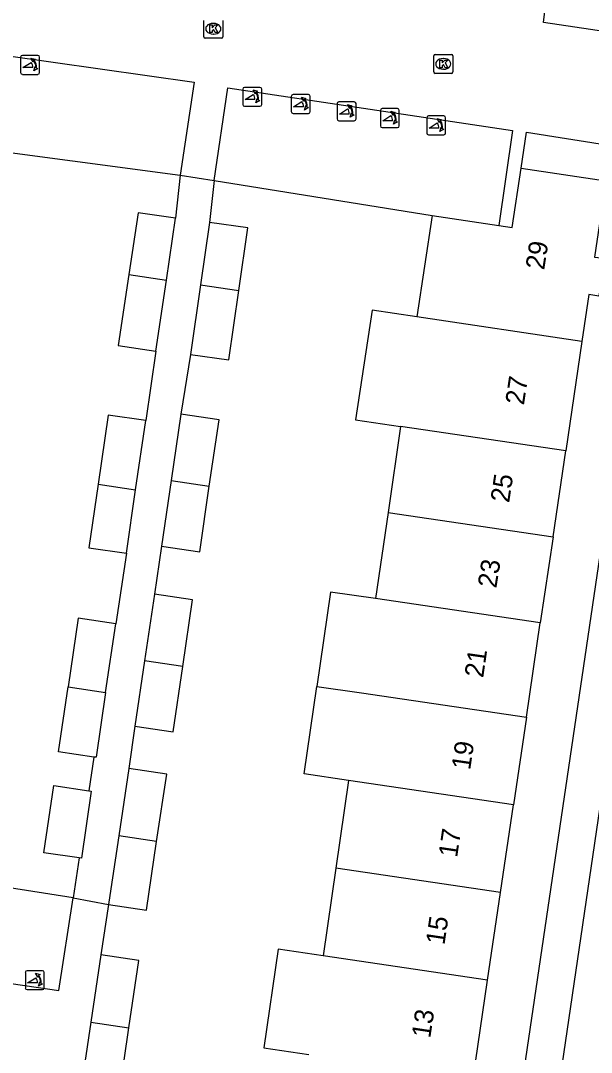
# Model space of a CAD drawing. Extents: x 164150 to 165261, y 382513 to 383432.
# Drawn here: x 164238.9 to 164268.9, y 382940.4 to 382994.8 of the extents above; entities that cross this region are included whole.
import ezdxf

# ---------------------------------------------------------------- set-up
doc = ezdxf.new("R2010")
doc.units = 0
for name, color, linetype in [('IMGEO_Kolk', 7, 'Continuous'), ('IMGEO_Pand', 7, 'Continuous'), ('IMGEO_Pand_nummerreeks', 7, 'Continuous'), ('IMGEO_Parkeervlak_open', 7, 'Continuous'), ('IMGEO_Poller', 7, 'Continuous'), ('IMGEO_Rijbaan_lokaal_open', 7, 'Continuous'), ('IMGEO_Voetpad_open', 7, 'Continuous')]:
    doc.layers.add(name, color=color, linetype=linetype)

msp = doc.modelspace()

# ---------------------------------------------------------------- linework, layer by layer
at = {"layer": 'IMGEO_Kolk'}
for p, q in [((164248.512, 382993.961), (164248.512, 382994.813)), ((164249.513, 382994.813), (164249.513, 382993.961)), ((164249, 382994.667), (164249.025, 382994.667)), ((164249.439, 382993.887), (164248.587, 382993.887)), ((164249.023, 382994.107), (164248.998, 382994.107)), ((164260.625, 382992.108), (164260.625, 382992.96)), ((164260.7, 382993.034), (164261.552, 382993.034)), ((164261.113, 382992.814), (164261.138, 382992.814)), ((164261.626, 382992.96), (164261.626, 382992.108)), ((164261.136, 382992.254), (164261.111, 382992.254)), ((164261.552, 382992.034), (164260.7, 382992.034))]:
    msp.add_line(p, q, dxfattribs=at)
for points in [[(164248.512, 382993.961), (164248.512, 382994.813)], [(164249.513, 382994.813), (164249.513, 382993.961)], [(164248.833, 382994.587), (164248.956, 382994.587), (164248.956, 382994.436), (164249.086, 382994.587), (164249.25, 382994.587), (164249.104, 382994.436), (164249.257, 382994.187), (164249.105, 382994.187), (164249.02, 382994.351), (164248.956, 382994.284), (164248.956, 382994.187), (164248.833, 382994.187), (164248.833, 382994.587)], [(164249.439, 382993.887), (164248.587, 382993.887)], [(164260.625, 382992.108), (164260.625, 382992.96)], [(164260.7, 382993.034), (164261.552, 382993.034)], [(164260.946, 382992.734), (164261.069, 382992.734), (164261.069, 382992.583), (164261.199, 382992.734), (164261.363, 382992.734), (164261.217, 382992.583), (164261.37, 382992.334), (164261.218, 382992.334), (164261.133, 382992.498), (164261.069, 382992.431), (164261.069, 382992.334), (164260.946, 382992.334), (164260.946, 382992.734)], [(164261.626, 382992.96), (164261.626, 382992.108)], [(164261.552, 382992.034), (164260.7, 382992.034)]]:
    msp.add_lwpolyline(points, dxfattribs=at)
for centre, start, end in [((164248.589, 382993.963), 181.552, 268.448), ((164248.589, 382993.963), 181.552, 268.448), ((164249.437, 382993.963), 271.552, 358.448), ((164249.437, 382993.963), 271.552, 358.448), ((164260.702, 382992.958), 91.552, 178.448), ((164260.702, 382992.958), 91.552, 178.448), ((164261.55, 382992.958), 1.552, 88.448), ((164261.55, 382992.958), 1.552, 88.448), ((164260.702, 382992.11), 181.552, 268.448), ((164260.702, 382992.11), 181.552, 268.448), ((164261.55, 382992.11), 271.552, 358.448), ((164261.55, 382992.11), 271.552, 358.448)]:
    msp.add_arc(centre, 0.0765, start, end, dxfattribs=at)
for centre, major_axis, ratio, start_param, end_param in [((164248.999, 382994.387), (-0.387, 0.002), 0.722429, 4.712389, 7.853982), ((164249.024, 382994.387), (-0.39, 0.002), 0.717154, 1.570796, 4.712389), ((164261.112, 382992.534), (-0.387, 0.002), 0.722429, 4.712389, 7.853982), ((164261.137, 382992.534), (-0.39, 0.002), 0.717154, 1.570796, 4.712389)]:
    msp.add_ellipse(centre, major_axis=major_axis, ratio=ratio, start_param=start_param, end_param=end_param, dxfattribs=at)
at = {"layer": 'IMGEO_Pand'}
for points in [[(164264.054, 382984.022), (164264.753, 382983.919), (164265.229, 382987.03)], [(164265.229, 382987.03), (164269.688, 382986.378), (164269.099, 382982.348), (164269.632, 382982.3), (164269.326, 382980.293), (164268.792, 382980.375), (164268.428, 382977.911)], [(164247.024, 382984.396), (164245.046, 382984.689), (164244.562, 382981.432)], [(164260.536, 382984.54), (164259.733, 382979.198)], [(164260.536, 382984.54), (164264.054, 382984.022)], [(164246.541, 382981.139), (164247.024, 382984.396)], [(164248.815, 382984.183), (164248.34, 382980.884)], [(164250.355, 382980.586), (164250.832, 382983.893), (164248.815, 382984.183)], [(164244.562, 382981.432), (164244.007, 382977.691), (164245.986, 382977.397)], [(164244.562, 382981.432), (164246.541, 382981.139)], [(164245.986, 382977.397), (164246.541, 382981.139)], [(164248.34, 382980.884), (164247.812, 382977.22)], [(164248.34, 382980.884), (164250.355, 382980.586)], [(164247.812, 382977.22), (164249.829, 382976.93), (164250.355, 382980.586)], [(164259.733, 382979.198), (164257.371, 382979.553), (164256.504, 382973.779), (164258.877, 382973.423)], [(164268.428, 382977.911), (164259.733, 382979.198)], [(164268.428, 382977.911), (164267.576, 382972.135)], [(164245.448, 382973.734), (164243.468, 382974.022), (164242.939, 382970.38)], [(164244.917, 382970.087), (164245.448, 382973.734)], [(164247.307, 382974.069), (164246.793, 382970.58)], [(164248.801, 382970.283), (164249.315, 382973.774), (164247.307, 382974.069)], [(164258.877, 382973.423), (164258.219, 382968.889)], [(164267.576, 382972.135), (164258.877, 382973.423)], [(164266.907, 382967.603), (164267.576, 382972.135)], [(164242.939, 382970.38), (164242.453, 382967.035), (164244.432, 382966.748)], [(164242.939, 382970.38), (164244.917, 382970.087)], [(164246.793, 382970.58), (164246.284, 382967.115)], [(164246.793, 382970.58), (164248.801, 382970.283)], [(164244.432, 382966.748), (164244.917, 382970.087)], [(164246.284, 382967.115), (164248.292, 382966.82), (164248.801, 382970.283)], [(164258.219, 382968.889), (164257.561, 382964.355)], [(164258.219, 382968.889), (164266.907, 382967.603)], [(164266.907, 382967.603), (164266.238, 382963.071)], [(164245.907, 382964.58), (164245.39, 382961.076)], [(164247.398, 382960.779), (164247.915, 382964.284), (164245.907, 382964.58)], [(164257.561, 382964.355), (164255.186, 382964.7), (164254.463, 382959.727)], [(164266.238, 382963.071), (164257.561, 382964.355)], [(164243.867, 382963.027), (164241.888, 382963.317), (164241.359, 382959.696)], [(164243.337, 382959.403), (164243.867, 382963.027)], [(164265.504, 382958.099), (164266.238, 382963.071)], [(164245.39, 382961.076), (164244.881, 382957.624)], [(164247.398, 382960.779), (164245.39, 382961.076)], [(164244.881, 382957.624), (164246.889, 382957.328), (164247.398, 382960.779)], [(164242.721, 382956.006), (164240.859, 382956.278), (164241.359, 382959.696)], [(164241.359, 382959.696), (164243.337, 382959.403)], [(164256.139, 382954.767), (164253.792, 382955.114), (164254.463, 382959.727)], [(164254.463, 382959.727), (164256.81, 382959.386), (164265.504, 382958.099)], [(164243.337, 382959.403), (164242.838, 382955.989), (164242.721, 382956.006)], [(164265.504, 382958.099), (164264.822, 382953.482)], [(164244.553, 382955.398), (164244.028, 382951.843)], [(164246.026, 382951.547), (164246.557, 382955.102), (164244.553, 382955.398)], [(164256.139, 382954.767), (164255.468, 382950.15)], [(164264.822, 382953.482), (164256.139, 382954.767)], [(164241.939, 382950.687), (164240.08, 382950.961), (164240.602, 382954.496), (164242.46, 382954.222)], [(164242.46, 382954.222), (164242.58, 382954.204), (164242.059, 382950.669), (164241.939, 382950.687)], [(164264.141, 382948.866), (164264.822, 382953.482)], [(164244.028, 382951.843), (164243.515, 382948.363), (164243.495, 382948.226)], [(164246.026, 382951.547), (164244.028, 382951.843)], [(164243.495, 382948.226), (164245.485, 382947.932), (164246.026, 382951.547)], [(164255.468, 382950.15), (164254.797, 382945.531)], [(164264.141, 382948.866), (164255.468, 382950.15)], [(164263.459, 382944.249), (164264.141, 382948.866)], [(164254.797, 382945.531), (164252.432, 382945.875), (164251.678, 382940.679), (164254.043, 382940.336)], [(164243.081, 382945.579), (164242.558, 382942.035)], [(164244.566, 382941.738), (164245.089, 382945.283), (164243.081, 382945.579)], [(164263.459, 382944.249), (164254.797, 382945.531)], [(164262.692, 382939.056), (164263.459, 382944.249)], [(164242.558, 382942.035), (164242.054, 382938.614)], [(164242.558, 382942.035), (164244.566, 382941.738)], [(164242.054, 382938.614), (164244.062, 382938.318), (164244.566, 382941.738)]]:
    msp.add_lwpolyline(points, dxfattribs=at)
at = {"layer": 'IMGEO_Parkeervlak_open'}
for points in [[(164235.9, 382988.175), (164247.26, 382986.674)], [(164249.057, 382986.385), (164260.536, 382984.54)], [(164241.628, 382948.582), (164230.313, 382950.35)]]:
    msp.add_lwpolyline(points, dxfattribs=at)
at = {"layer": 'IMGEO_Poller'}
for p, q in [((164238.861, 382992.885), (164238.861, 382992.078)), ((164238.861, 382992.885), (164238.861, 382992.078)), ((164239.763, 382992.98), (164238.955, 382992.98)), ((164239.763, 382992.98), (164238.955, 382992.98)), ((164239.857, 382992.078), (164239.857, 382992.885)), ((164239.857, 382992.078), (164239.857, 382992.885)), ((164238.955, 382991.983), (164239.763, 382991.983)), ((164238.955, 382991.983), (164239.763, 382991.983)), ((164250.563, 382991.202), (164250.563, 382990.395)), ((164250.563, 382991.202), (164250.563, 382990.395)), ((164251.465, 382991.297), (164250.657, 382991.297)), ((164251.465, 382991.297), (164250.657, 382991.297)), ((164251.559, 382990.395), (164251.559, 382991.202)), ((164251.559, 382990.395), (164251.559, 382991.202)), ((164253.119, 382990.823), (164253.119, 382990.016)), ((164253.119, 382990.823), (164253.119, 382990.016)), ((164254.021, 382990.918), (164253.213, 382990.918)), ((164254.021, 382990.918), (164253.213, 382990.918)), ((164254.115, 382990.016), (164254.115, 382990.823)), ((164254.115, 382990.016), (164254.115, 382990.823)), ((164255.532, 382990.439), (164255.532, 382989.632)), ((164255.532, 382990.439), (164255.532, 382989.632)), ((164256.434, 382990.534), (164255.626, 382990.534)), ((164256.434, 382990.534), (164255.626, 382990.534)), ((164256.528, 382989.632), (164256.528, 382990.439)), ((164256.528, 382989.632), (164256.528, 382990.439)), ((164250.657, 382990.3), (164251.465, 382990.3)), ((164250.657, 382990.3), (164251.465, 382990.3)), ((164253.213, 382989.921), (164254.021, 382989.921)), ((164253.213, 382989.921), (164254.021, 382989.921)), ((164257.813, 382990.081), (164257.813, 382989.274)), ((164257.813, 382990.081), (164257.813, 382989.274)), ((164258.715, 382990.176), (164257.907, 382990.176)), ((164258.715, 382990.176), (164257.907, 382990.176)), ((164258.809, 382989.274), (164258.809, 382990.081)), ((164258.809, 382989.274), (164258.809, 382990.081)), ((164255.626, 382989.537), (164256.434, 382989.537)), ((164255.626, 382989.537), (164256.434, 382989.537)), ((164260.253, 382989.695), (164260.253, 382988.888)), ((164260.253, 382989.695), (164260.253, 382988.888)), ((164261.155, 382989.79), (164260.347, 382989.79)), ((164261.155, 382989.79), (164260.347, 382989.79)), ((164261.249, 382988.888), (164261.249, 382989.695)), ((164261.249, 382988.888), (164261.249, 382989.695)), ((164257.907, 382989.179), (164258.715, 382989.179)), ((164257.907, 382989.179), (164258.715, 382989.179)), ((164260.347, 382988.793), (164261.155, 382988.793)), ((164260.347, 382988.793), (164261.155, 382988.793)), ((164239.108, 382944.65), (164239.108, 382943.843)), ((164239.108, 382944.65), (164239.108, 382943.843)), ((164240.01, 382944.745), (164239.202, 382944.745)), ((164240.01, 382944.745), (164239.202, 382944.745)), ((164240.104, 382943.843), (164240.104, 382944.65)), ((164240.104, 382943.843), (164240.104, 382944.65)), ((164239.202, 382943.748), (164240.01, 382943.748)), ((164239.202, 382943.748), (164240.01, 382943.748))]:
    msp.add_line(p, q, dxfattribs=at)
for points in [[(164239.496, 382992.336), (164238.983, 382992.336), (164239.413, 382992.611)], [(164239.54, 382992.709), (164239.528, 382992.636), (164239.403, 382992.841)], [(164239.403, 382992.841), (164239.634, 382992.775), (164239.563, 382992.743)], [(164239.556, 382992.164), (164239.622, 382992.395), (164239.652, 382992.327)], [(164239.688, 382992.3), (164239.76, 382992.289), (164239.556, 382992.164)], [(164251.242, 382991.026), (164251.23, 382990.953), (164251.105, 382991.158)], [(164251.105, 382991.158), (164251.336, 382991.092), (164251.265, 382991.06)], [(164251.198, 382990.653), (164250.685, 382990.653), (164251.115, 382990.928)], [(164251.258, 382990.481), (164251.324, 382990.712), (164251.354, 382990.644)], [(164251.39, 382990.617), (164251.462, 382990.606), (164251.258, 382990.481)], [(164253.754, 382990.274), (164253.241, 382990.274), (164253.671, 382990.549)], [(164253.798, 382990.647), (164253.786, 382990.574), (164253.661, 382990.779)], [(164253.661, 382990.779), (164253.892, 382990.713), (164253.821, 382990.681)], [(164253.814, 382990.102), (164253.88, 382990.333), (164253.91, 382990.265)], [(164253.946, 382990.238), (164254.018, 382990.227), (164253.814, 382990.102)], [(164256.167, 382989.89), (164255.654, 382989.89), (164256.084, 382990.165)], [(164256.211, 382990.263), (164256.199, 382990.19), (164256.074, 382990.395)], [(164256.074, 382990.395), (164256.305, 382990.329), (164256.234, 382990.297)], [(164256.227, 382989.718), (164256.293, 382989.949), (164256.323, 382989.881)], [(164258.492, 382989.905), (164258.48, 382989.832), (164258.355, 382990.037)], [(164258.355, 382990.037), (164258.586, 382989.971), (164258.515, 382989.939)], [(164256.359, 382989.854), (164256.431, 382989.843), (164256.227, 382989.718)], [(164258.448, 382989.532), (164257.935, 382989.532), (164258.365, 382989.807)], [(164258.508, 382989.36), (164258.574, 382989.591), (164258.604, 382989.523)], [(164258.64, 382989.496), (164258.712, 382989.485), (164258.508, 382989.36)], [(164260.888, 382989.146), (164260.375, 382989.146), (164260.805, 382989.421)], [(164260.932, 382989.519), (164260.92, 382989.446), (164260.795, 382989.651)], [(164260.795, 382989.651), (164261.026, 382989.585), (164260.955, 382989.553)], [(164260.948, 382988.974), (164261.014, 382989.205), (164261.044, 382989.137)], [(164261.08, 382989.11), (164261.152, 382989.099), (164260.948, 382988.974)], [(164239.743, 382944.101), (164239.23, 382944.101), (164239.66, 382944.376)], [(164239.787, 382944.474), (164239.775, 382944.401), (164239.65, 382944.606)], [(164239.65, 382944.606), (164239.881, 382944.54), (164239.81, 382944.508)], [(164239.803, 382943.929), (164239.869, 382944.16), (164239.899, 382944.092)], [(164239.935, 382944.065), (164240.007, 382944.054), (164239.803, 382943.929)]]:
    msp.add_lwpolyline(points, dxfattribs=at)
for centre, radius, start, end in [((164238.955, 382992.885), 0.0946, 90, 180), ((164238.955, 382992.885), 0.0946, 90, 180), ((164239.168, 382992.386), 0.332, 351.3247, 42.4854), ((164239.182, 382992.396), 0.476, 351.7527, 41.1691), ((164239.182, 382992.396), 0.516, 349.3569, 42.2912), ((164239.763, 382992.885), 0.0946, 0, 90), ((164239.763, 382992.885), 0.0946, 0, 90), ((164238.955, 382992.078), 0.0946, 180, 270), ((164238.955, 382992.078), 0.0946, 180, 270), ((164239.763, 382992.078), 0.0946, 270, 0), ((164239.763, 382992.078), 0.0946, 270, 0), ((164250.657, 382991.202), 0.0946, 90, 180), ((164250.657, 382991.202), 0.0946, 90, 180), ((164250.884, 382990.713), 0.476, 351.7527, 41.1691), ((164250.884, 382990.713), 0.516, 349.3569, 42.2912), ((164251.465, 382991.202), 0.0946, 0, 90), ((164251.465, 382991.202), 0.0946, 0, 90), ((164250.87, 382990.703), 0.332, 351.3247, 42.4854), ((164253.213, 382990.823), 0.0946, 90, 180), ((164253.213, 382990.823), 0.0946, 90, 180), ((164253.426, 382990.324), 0.332, 351.3247, 42.4854), ((164253.44, 382990.334), 0.476, 351.7527, 41.1691), ((164253.44, 382990.334), 0.516, 349.3569, 42.2912), ((164254.021, 382990.823), 0.0946, 0, 90), ((164254.021, 382990.823), 0.0946, 0, 90), ((164255.626, 382990.439), 0.0946, 90, 180), ((164255.626, 382990.439), 0.0946, 90, 180), ((164256.434, 382990.439), 0.0946, 0, 90), ((164256.434, 382990.439), 0.0946, 0, 90), ((164250.657, 382990.395), 0.0946, 180, 270), ((164250.657, 382990.395), 0.0946, 180, 270), ((164251.465, 382990.395), 0.0946, 270, 0), ((164251.465, 382990.395), 0.0946, 270, 0), ((164253.213, 382990.016), 0.0946, 180, 270), ((164253.213, 382990.016), 0.0946, 180, 270), ((164254.021, 382990.016), 0.0946, 270, 0), ((164254.021, 382990.016), 0.0946, 270, 0), ((164255.839, 382989.94), 0.332, 351.3247, 42.4854), ((164255.853, 382989.95), 0.476, 351.7527, 41.1691), ((164255.853, 382989.95), 0.516, 349.3569, 42.2912), ((164257.907, 382990.081), 0.0946, 90, 180), ((164257.907, 382990.081), 0.0946, 90, 180), ((164258.134, 382989.592), 0.476, 351.7527, 41.1691), ((164258.134, 382989.592), 0.516, 349.3569, 42.2912), ((164258.715, 382990.081), 0.0946, 0, 90), ((164258.715, 382990.081), 0.0946, 0, 90), ((164255.626, 382989.632), 0.0946, 180, 270), ((164255.626, 382989.632), 0.0946, 180, 270), ((164256.434, 382989.632), 0.0946, 270, 0), ((164256.434, 382989.632), 0.0946, 270, 0), ((164258.12, 382989.582), 0.332, 351.3247, 42.4854), ((164260.347, 382989.695), 0.0946, 90, 180), ((164260.347, 382989.695), 0.0946, 90, 180), ((164260.56, 382989.196), 0.332, 351.3247, 42.4854), ((164260.574, 382989.206), 0.476, 351.7527, 41.1691), ((164260.574, 382989.206), 0.516, 349.3569, 42.2912), ((164261.155, 382989.695), 0.0946, 0, 90), ((164261.155, 382989.695), 0.0946, 0, 90), ((164257.907, 382989.274), 0.0946, 180, 270), ((164257.907, 382989.274), 0.0946, 180, 270), ((164258.715, 382989.274), 0.0946, 270, 0), ((164258.715, 382989.274), 0.0946, 270, 0), ((164260.347, 382988.888), 0.0946, 180, 270), ((164260.347, 382988.888), 0.0946, 180, 270), ((164261.155, 382988.888), 0.0946, 270, 0), ((164261.155, 382988.888), 0.0946, 270, 0), ((164239.202, 382944.65), 0.0946, 90, 180), ((164239.202, 382944.65), 0.0946, 90, 180), ((164239.415, 382944.151), 0.332, 351.3247, 42.4854), ((164239.429, 382944.161), 0.476, 351.7527, 41.1691), ((164239.429, 382944.161), 0.516, 349.3569, 42.2912), ((164240.01, 382944.65), 0.0946, 0, 90), ((164240.01, 382944.65), 0.0946, 0, 90), ((164239.202, 382943.843), 0.0946, 180, 270), ((164239.202, 382943.843), 0.0946, 180, 270), ((164240.01, 382943.843), 0.0946, 270, 0), ((164240.01, 382943.843), 0.0946, 270, 0)]:
    msp.add_arc(centre, radius, start, end, dxfattribs=at)
at = {"layer": 'IMGEO_Rijbaan_lokaal_open'}
for points in [[(164273.356, 382993.681), (164266.411, 382994.722), (164266.632, 382996.57)], [(164232.367, 382988.7), (164233.128, 382993.672), (164248.002, 382991.565), (164247.26, 382986.674)], [(164249.057, 382986.385), (164249.772, 382991.276), (164264.768, 382989.02), (164264.054, 382984.022)], [(164265.229, 382987.03), (164265.514, 382988.929), (164272.503, 382987.831)], [(164247.26, 382986.674), (164249.057, 382986.385)], [(164226.796, 382950.871), (164226.036, 382945.883), (164240.878, 382943.694), (164241.628, 382948.582)], [(164241.628, 382948.582), (164243.495, 382948.226)], [(164243.495, 382948.226), (164243.081, 382945.579)]]:
    msp.add_lwpolyline(points, dxfattribs=at)
at = {"layer": 'IMGEO_Voetpad_open'}
for points in [[(164272.503, 382987.831), (164260.833, 382908.792)], [(164247.26, 382986.674), (164247.024, 382984.396)], [(164249.057, 382986.385), (164248.815, 382984.183)], [(164266.749, 382935.45), (164273.731, 382982.918)], [(164245.986, 382977.397), (164245.448, 382973.734)], [(164247.812, 382977.22), (164247.307, 382974.069)], [(164246.284, 382967.115), (164245.907, 382964.58)], [(164244.432, 382966.748), (164243.867, 382963.027)], [(164244.881, 382957.624), (164244.553, 382955.398)], [(164242.721, 382956.006), (164242.46, 382954.222)], [(164241.939, 382950.687), (164241.628, 382948.582)]]:
    msp.add_lwpolyline(points, dxfattribs=at)

# ---------------------------------------------------------------- texts
at = {"layer": 'IMGEO_Pand_nummerreeks'}
for s, rotation, p in [('29', 81.2745, (164266.439, 382981.642)), ('27', 81.4111, (164265.37, 382974.522)), ('25', 81.4652, (164264.593, 382969.375)), ('23', 81.0827, (164263.918, 382964.873)), ('21', 81.7247, (164263.226, 382960.152)), ('19', 81.5204, (164262.539, 382955.291)), ('17', 81.5879, (164261.852, 382950.677)), ('15', 81.6114, (164261.184, 382946.07)), ('13', 81.5289, (164260.438, 382941.158))]:
    msp.add_text(s, height=1, rotation=rotation, dxfattribs=at).set_placement(p)

doc.saveas('drawing.dxf')
